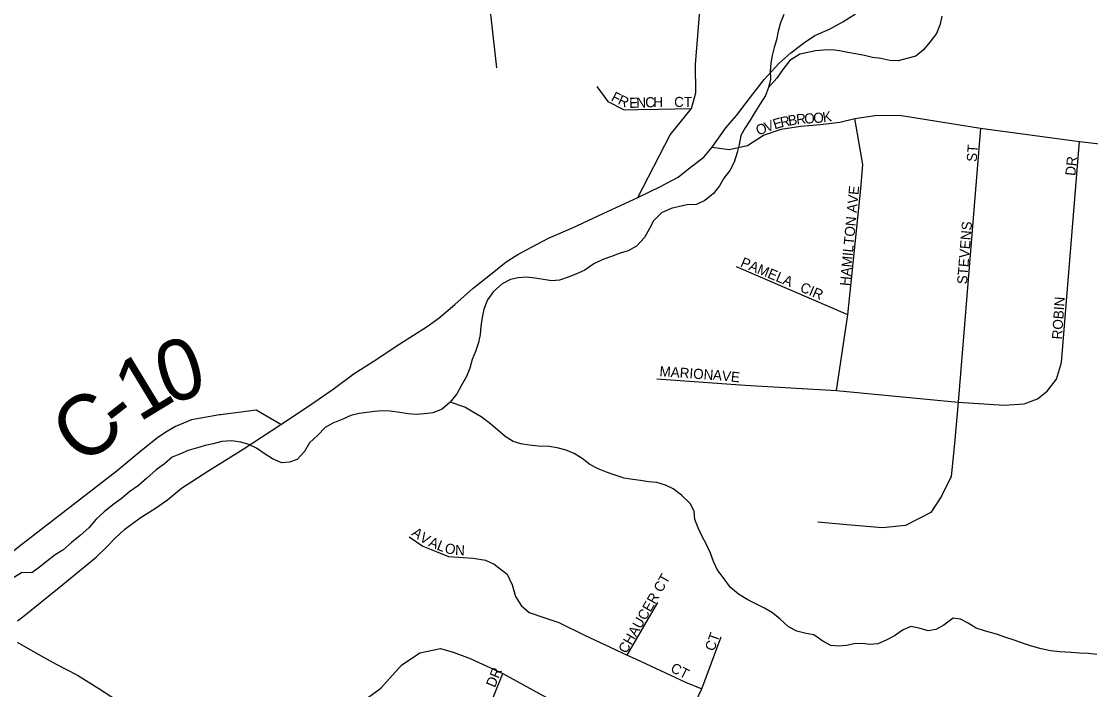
# Model space of a CAD drawing. Extents: x 0 to 1064, y 0 to 440.
# Drawn here: x 203.95 to 220.01, y 114.02 to 124.05 of the extents above; entities that cross this region are included whole.
import ezdxf

# ---------------------------------------------------------------- set-up
doc = ezdxf.new("R2010")
doc.units = 0
for name, color, linetype in [('GM_X_County_Road', 7, 'Continuous'), ('GM_X_County_Road_Text', 7, 'Continuous'), ('GM_X_Minor_River', 7, 'Continuous'), ('GM_X_Township_Road', 7, 'Continuous'), ('GM_X_Township_Subdivision', 7, 'Continuous'), ('GM_X_Township_Subdivision_Text', 7, 'Continuous'), ('GM_X_US_Route', 7, 'Continuous')]:
    doc.layers.add(name, color=color, linetype=linetype)

msp = doc.modelspace()

# ---------------------------------------------------------------- linework, layer by layer
at = {"layer": 'GM_X_County_Road'}
for points in [[(206.941, 118.144), (206.924, 118.142), (206.503, 118.067), (206.264, 117.969), (206.118, 117.883), (205.994, 117.799), (205.748, 117.604), (205.39, 117.306), (203.914, 116.161), (203.724, 116.012), (203.483, 115.836), (203.268, 115.716), (202.892, 115.573), (202.458, 115.438), (202.035, 115.304), (201.774, 115.218), (201.585, 115.159), (201.426, 115.11)], [(207.849, 117.997), (207.478, 118.214), (206.941, 118.144)], [(203.887, 114.732), (204.157, 114.577), (204.472, 114.403), (204.794, 114.236), (205.112, 114.037), (206.021, 113.449), (206.502, 113.223), (206.805, 113.159), (207.012, 113.116), (207.261, 113.128), (207.537, 113.185), (207.906, 113.362), (209.036, 113.811), (209.35, 114.042), (209.658, 114.388), (209.937, 114.57), (210.246, 114.637), (210.434, 114.582), (210.694, 114.485), (211.183, 114.26), (211.939, 113.849), (213.561, 112.75), (213.878, 112.52), (214.152, 112.33)]]:
    msp.add_lwpolyline(points, dxfattribs=at)
at = {"layer": 'GM_X_Minor_River'}
for points in [[(215.402, 124.155), (215.352, 124.028), (215.319, 123.901), (215.293, 123.774), (215.26, 123.659), (215.228, 123.538), (215.208, 123.423), (215.2, 123.308), (215.204, 123.18), (215.171, 123.059), (215.127, 122.938), (215.046, 122.812), (214.971, 122.692), (214.896, 122.565), (214.821, 122.451), (214.758, 122.336), (214.732, 122.203), (214.705, 122.082), (214.66, 121.937), (214.591, 121.81), (214.504, 121.696), (214.435, 121.582), (214.348, 121.468), (214.219, 121.361), (214.09, 121.302), (213.95, 121.298), (213.834, 121.27), (213.712, 121.241), (213.565, 121.177), (213.448, 121.057), (213.385, 120.943), (213.31, 120.804), (213.192, 120.678), (213.064, 120.608), (212.947, 120.573), (212.904, 120.556)], [(217.779, 124.129), (217.753, 124.008), (217.696, 123.869), (217.596, 123.737), (217.503, 123.623), (217.386, 123.528), (217.252, 123.494), (217.123, 123.459), (216.996, 123.461), (216.863, 123.494), (216.735, 123.508), (216.614, 123.54), (216.481, 123.561), (216.366, 123.581), (216.238, 123.607), (216.123, 123.621), (216.001, 123.617), (215.88, 123.607), (215.764, 123.584), (215.642, 123.556), (215.494, 123.461), (215.389, 123.329), (215.301, 123.197), (215.171, 123.059)], [(212.904, 120.556), (212.813, 120.52), (212.684, 120.474), (212.55, 120.409), (212.414, 120.314), (212.28, 120.256), (212.163, 120.209), (212.035, 120.168), (211.913, 120.158), (211.792, 120.178), (211.665, 120.198), (211.537, 120.213), (211.415, 120.202), (211.299, 120.174), (211.171, 120.109), (211.041, 119.996), (210.954, 119.87), (210.897, 119.731), (210.87, 119.604), (210.85, 119.476), (210.842, 119.349), (210.816, 119.228), (210.771, 119.095), (210.72, 118.974), (210.688, 118.847), (210.637, 118.72), (210.556, 118.582), (210.493, 118.461), (210.393, 118.335), (210.27, 118.228), (210.129, 118.175), (210.007, 118.159), (209.886, 118.149), (209.758, 118.157), (209.637, 118.177), (209.491, 118.198), (209.376, 118.206), (209.254, 118.195), (209.138, 118.179), (209.023, 118.163), (208.901, 118.134), (208.778, 118.081), (208.631, 118.017), (208.515, 117.952), (208.403, 117.838), (208.28, 117.725), (208.205, 117.592), (208.093, 117.473)], [(212.132, 117.615), (211.999, 117.647), (211.878, 117.668), (211.72, 117.676), (211.58, 117.69), (211.453, 117.711), (211.338, 117.743), (211.218, 117.818), (211.104, 117.917), (210.978, 118.022), (210.858, 118.115), (210.737, 118.184), (210.611, 118.259), (210.393, 118.335)], [(208.093, 117.473), (207.977, 117.432), (207.861, 117.422), (207.723, 117.485), (207.596, 117.566), (207.482, 117.646), (207.367, 117.697), (207.246, 117.735), (207.113, 117.756), (206.961, 117.746), (206.833, 117.711), (206.711, 117.683), (206.595, 117.648), (206.454, 117.608), (206.338, 117.561), (206.215, 117.509), (206.098, 117.407), (205.975, 117.318), (205.833, 117.193), (205.71, 117.085), (205.581, 116.996), (205.451, 116.883), (205.322, 116.794), (205.193, 116.687), (205.075, 116.579), (204.964, 116.447), (204.834, 116.334), (204.705, 116.226), (204.575, 116.113), (204.458, 116.042), (204.341, 115.953), (204.224, 115.857), (204.107, 115.774), (203.952, 115.779)], [(212.975, 117.203), (212.856, 117.245), (212.741, 117.283), (212.614, 117.334), (212.487, 117.397), (212.373, 117.489), (212.253, 117.564), (212.132, 117.615)], [(220.106, 114.547), (219.979, 114.561), (219.845, 114.569), (219.718, 114.578), (219.548, 114.586), (219.408, 114.601), (219.269, 114.633), (219.111, 114.678), (218.99, 114.717), (218.863, 114.761), (218.724, 114.806), (218.597, 114.851), (218.416, 114.902), (218.295, 114.94), (218.175, 115.015), (218.06, 115.078), (217.945, 115.092), (217.809, 114.985), (217.687, 114.92), (217.571, 114.903), (217.438, 114.942), (217.311, 114.968), (217.194, 114.915), (217.065, 114.826), (216.93, 114.756), (216.814, 114.709), (216.698, 114.699), (216.583, 114.713), (216.461, 114.708), (216.345, 114.68), (216.23, 114.67), (216.108, 114.684), (215.988, 114.746), (215.855, 114.84), (215.74, 114.86), (215.601, 114.898), (215.474, 114.961), (215.349, 115.079), (215.235, 115.171), (215.114, 115.24), (214.982, 115.309), (214.861, 115.366), (214.723, 115.453), (214.603, 115.552), (214.508, 115.681), (214.401, 115.823), (214.348, 115.945), (214.301, 116.067), (214.243, 116.196), (214.178, 116.318), (214.119, 116.447), (214.067, 116.575), (214.056, 116.697), (213.998, 116.813), (213.866, 116.937), (213.74, 117.036), (213.625, 117.087), (213.498, 117.131), (213.371, 117.139), (213.249, 117.16), (213.134, 117.174), (213.001, 117.194), (212.975, 117.203)], [(201.959, 114.463), (202.264, 114.765), (202.584, 115.002), (202.909, 115.19), (203.229, 115.342), (203.542, 115.524), (203.849, 115.712), (203.952, 115.779)]]:
    msp.add_lwpolyline(points, dxfattribs=at)
at = {"layer": 'GM_X_Township_Road'}
msp.add_lwpolyline([(213.212, 121.405), (213.697, 122.349), (214.018, 122.741), (214.081, 122.977), (214.077, 123.401), (214.238, 125.397)], dxfattribs=at)
at = {"layer": 'GM_X_Township_Subdivision'}
for points in [[(211.093, 123.351), (211.012, 124.068), (210.908, 124.986)], [(212.595, 123.071), (212.761, 122.845), (213.003, 122.723), (213.212, 122.729), (213.521, 122.734), (214.018, 122.741)], [(214.327, 122.163), (214.581, 122.128), (214.859, 122.187), (215.096, 122.341), (215.363, 122.43), (215.653, 122.477), (215.955, 122.501), (216.245, 122.537), (216.47, 122.59), (216.772, 122.637), (217.139, 122.643), (218.359, 122.448), (219.847, 122.245), (221.407, 122.067)], [(216.193, 118.508), (216.366, 119.645), (216.559, 121.536), (216.588, 121.903), (216.47, 122.59)], [(218.359, 122.448), (218.024, 118.335), (218.024, 118.334)], [(218.024, 118.335), (218.716, 118.287), (219.013, 118.308), (219.213, 118.384), (219.358, 118.497), (219.499, 118.681), (219.574, 118.93), (219.847, 122.245)], [(216.366, 119.645), (214.693, 120.365)], [(213.497, 118.686), (214.821, 118.589), (216.193, 118.508), (218.024, 118.335)], [(218.024, 118.334), (217.97, 117.714), (217.916, 117.217), (217.77, 116.925), (217.611, 116.68), (217.23, 116.483), (216.884, 116.45), (216.35, 116.493), (215.912, 116.531)], [(209.773, 116.311), (209.979, 116.174), (210.179, 116.092), (210.367, 116.017), (210.736, 115.992), (210.923, 115.961), (211.054, 115.905), (211.248, 115.755), (211.321, 115.591), (211.373, 115.419), (211.458, 115.283), (211.579, 115.176), (211.828, 115.091), (212.023, 115.029), (212.411, 114.835), (212.72, 114.692), (213.049, 114.538), (213.183, 114.477), (213.478, 114.341), (213.925, 114.131), (214.17, 114.032)], [(213.049, 114.538), (213.509, 115.325)], [(213.561, 112.75), (214.17, 114.032), (214.46, 114.811)], [(208.712, 110.311), (208.974, 110.686), (209.155, 110.979), (209.258, 111.08), (209.398, 111.177), (209.662, 111.221), (209.898, 111.304), (210.037, 111.428), (210.181, 111.733), (210.26, 111.972), (210.387, 112.29), (210.914, 113.589), (211.183, 114.26)]]:
    msp.add_lwpolyline(points, dxfattribs=at)
at = {"layer": 'GM_X_US_Route'}
for points in [[(208.114, 118.176), (208.33, 118.321), (208.633, 118.531), (208.95, 118.765), (209.235, 118.945), (209.637, 119.212), (210.045, 119.468), (210.226, 119.602), (210.462, 119.802), (210.736, 120.043), (211.022, 120.272), (211.234, 120.442), (211.407, 120.552), (211.611, 120.661), (211.87, 120.794), (212.227, 120.953), (212.688, 121.165), (213.212, 121.405), (213.551, 121.571), (213.816, 121.709), (213.996, 121.856), (214.201, 122.014), (214.327, 122.163), (214.53, 122.454), (214.693, 122.637), (214.902, 122.91), (215.11, 123.178), (215.329, 123.42), (215.51, 123.579), (215.697, 123.725), (215.87, 123.836), (216.091, 123.933), (216.289, 124.042), (216.481, 124.164)], [(203.891, 115.052), (203.973, 115.113), (204.52, 115.553), (205.074, 116.01), (205.23, 116.158), (205.362, 116.299), (205.505, 116.429), (205.735, 116.598), (205.964, 116.744), (206.143, 116.866), (206.355, 117.042), (206.751, 117.298), (207.283, 117.629), (207.849, 117.997), (208.114, 118.176)]]:
    msp.add_lwpolyline(points, dxfattribs=at)

# ---------------------------------------------------------------- texts
at = {"layer": 'GM_X_County_Road_Text'}
for s, rotation, p in [('0', 17.2056, (206.136, 118.289)), ('1', 31.3451, (205.715, 118.024)), ('C', 38.2022, (204.865, 117.355)), ('-', 37.9392, (205.446, 117.813))]:
    msp.add_text(s, height=0.909, rotation=rotation, dxfattribs=at).set_placement(p)
at = {"layer": 'GM_X_Township_Subdivision_Text'}
for s, height, rotation, p in [('F', 0.152, 332.702, (212.798, 122.867)), ('R', 0.152, 335.1932, (212.899, 122.815)), ('E', 0.152, 1.4759, (213.082, 122.75)), ('N', 0.152, 1.864, (213.19, 122.753)), ('C', 0.152, 2.3803, (213.325, 122.757)), ('H', 0.152, 1.2021, (213.444, 122.762)), ('CT', 0.1515, 0, (213.756, 122.765)), ('V', 0.152, 19.4303, (215.142, 122.384)), ('E', 0.152, 16.6286, (215.266, 122.428)), ('R', 0.152, 11.5147, (215.365, 122.458)), ('B', 0.152, 10.0094, (215.481, 122.482)), ('R', 0.152, 5.887, (215.597, 122.502)), ('O', 0.152, 2.7773, (215.714, 122.514)), ('O', 0.152, 4.6549, (215.852, 122.521)), ('K', 0.152, 9.0851, (215.998, 122.533)), ('O', 0.152, 22.4467, (215.021, 122.334)), ('ST', 0.1515, 86.1879, (218.301, 121.938)), ('DR', 0.1515, 83.9934, (219.781, 121.726)), ('HAMILTON AVE', 0.15152, 84.6115, (216.395, 120.073)), ('STEVENS', 0.1515, 85.3167, (218.155, 120.099)), ('PAMELA', 0.1515, 337.4581, (214.741, 120.376)), ('CIR', 0.1515, 336.8039, (215.634, 120.003)), ('ROBIN', 0.1515, 86.0112, (219.581, 119.272)), ('MARION', 0.1515, 355.9127, (213.532, 118.725)), ('AVE', 0.1515, 354.0969, (214.333, 118.672)), ('A', 0.152, 324.0176, (209.8, 116.346)), ('V', 0.152, 328.0908, (209.918, 116.261)), ('A', 0.152, 337.4122, (210.055, 116.178)), ('L', 0.152, 337.858, (210.179, 116.127)), ('O', 0.152, 344.7957, (210.297, 116.08)), ('N', 0.152, 358.0225, (210.463, 116.039)), ('CHAUCER CT', 0.1515, 59.9301, (213.038, 114.551)), ('CT', 0.1515, 70.5721, (214.356, 114.586)), ('CT', 0.1515, 333.435, (213.689, 114.295)), ('DR', 0.1515, 67.6179, (211.063, 114.041))]:
    msp.add_text(s, height=height, rotation=rotation, dxfattribs=at).set_placement(p)

doc.saveas('drawing.dxf')
